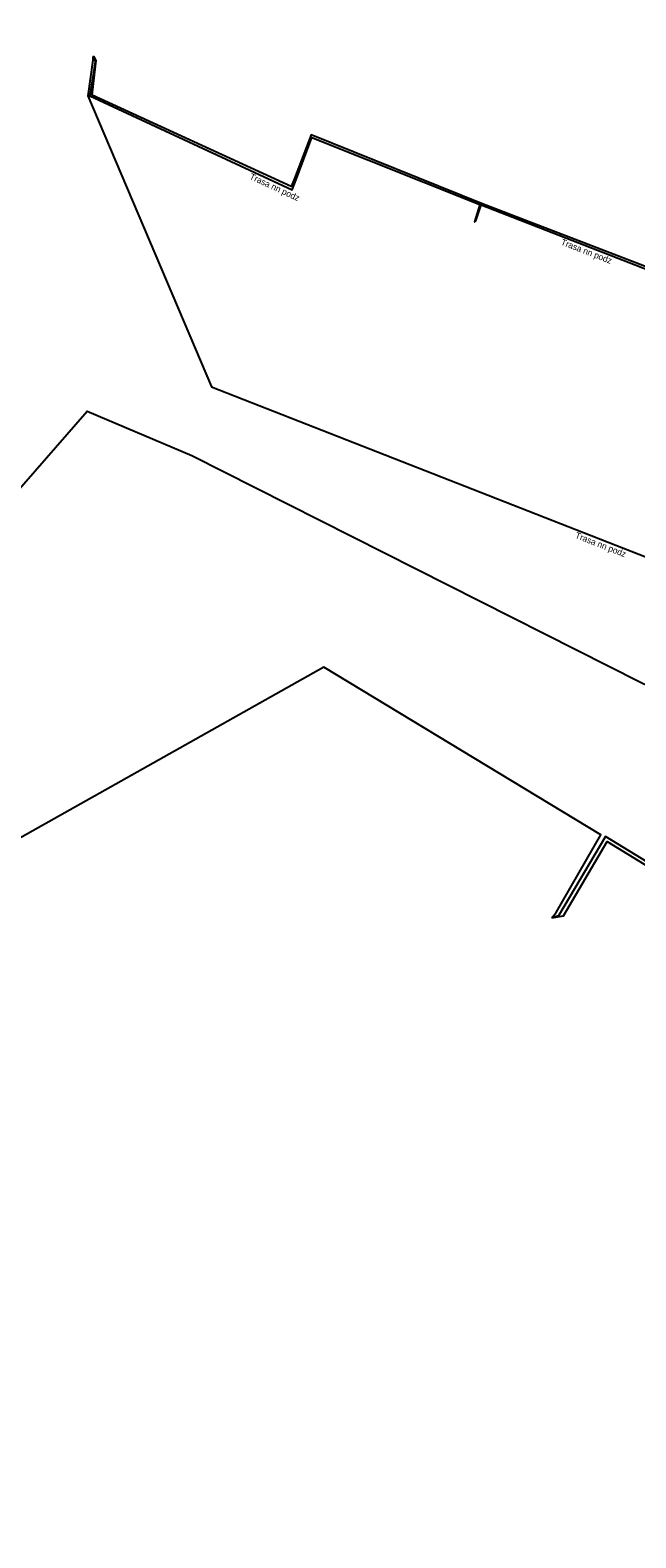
# Model space of a CAD drawing. Extents: x -875087 to -874407, y -1056142 to -1055396.
# Drawn here: x -874887.3 to -874839.3, y -1055781.1 to -1055661.4 of the extents above; entities that cross this region are included whole.
import ezdxf

# ---------------------------------------------------------------- set-up
doc = ezdxf.new("R2010")
doc.units = 0
for name, color, linetype in [('Popiskový text - Ostatní atributy Trasy', 7, 'Continuous'), ('Spojnice NN', 7, 'Continuous'), ('Spojnice VN', 7, 'Continuous')]:
    doc.layers.add(name, color=color, linetype=linetype)

msp = doc.modelspace()

# ---------------------------------------------------------------- linework, layer by layer
at = {"layer": 'Spojnice NN'}
for points in [[(-874845.94, -1055731.88), (-874845.61, -1055731.46), (-874842.04, -1055725.31), (-874864.03, -1055712), (-874900.7, -1055732.61), (-874967.78, -1055686.93), (-874987.15, -1055678.46), (-875041.7, -1055654.87), (-875087.2, -1055633.97), (-875087.28, -1055633.14), (-875080.46, -1055597.61), (-875077.09, -1055578.01), (-875076.82, -1055576.68), (-875075.98, -1055574.23)], [(-874882.28, -1055663.5), (-874882.36, -1055663.59), (-874882.36, -1055663.82), (-874882.76, -1055666.65), (-874872.96, -1055689.73), (-874796.22, -1055719.8), (-874798.83, -1055725.48), (-874799.67, -1055725.09), (-874804.68, -1055720.7), (-874805.36, -1055720.41)], [(-874882.28, -1055663.5), (-874882.18, -1055663.95), (-874882.6, -1055666.65), (-874866.55, -1055674.09), (-874866.23, -1055673.27), (-874864.99, -1055669.94), (-874851.66, -1055675.27), (-874852.09, -1055676.63), (-874852.1, -1055676.64)], [(-874805.36, -1055720.41), (-874804.9, -1055720.8), (-874799.91, -1055725.54), (-874798.64, -1055726.13), (-874789.31, -1055712.72), (-874783.85, -1055701.53), (-874805.68, -1055692.82), (-874813.18, -1055689.95), (-874832.53, -1055682.5), (-874851.52, -1055675.19), (-874865.05, -1055669.73), (-874866.37, -1055673.2), (-874866.62, -1055673.84), (-874882.43, -1055666.59), (-874882.1, -1055663.85), (-874882.28, -1055663.5)], [(-874852.1, -1055676.64), (-874852.08, -1055676.64), (-874851.97, -1055676.56), (-874851.55, -1055675.3), (-874832.62, -1055682.67), (-874833.06, -1055684.02), (-874833.07, -1055684.04)], [(-874805.36, -1055720.41), (-874805.14, -1055721.03), (-874800.48, -1055726.7), (-874798.71, -1055727.46), (-874800.13, -1055730), (-874809.2, -1055745.39), (-874829.16, -1055733.07), (-874841.67, -1055725.43), (-874845.42, -1055731.72), (-874845.94, -1055731.88)], [(-874845.94, -1055731.88), (-874845.02, -1055731.73), (-874841.56, -1055725.84), (-874809.29, -1055745.59), (-874821.17, -1055764.82), (-874859.09, -1055825.25), (-874862.21, -1055821.34), (-874862.58, -1055821)]]:
    msp.add_lwpolyline(points, dxfattribs=at)
at = {"layer": 'Spojnice VN'}
msp.add_lwpolyline([(-874889.46, -1055699.29), (-874882.83, -1055691.67), (-874874.5, -1055695.2), (-874838.9, -1055713.19), (-874822.22, -1055721.14), (-874812.85, -1055722.73), (-874801.88, -1055728.65), (-874799.88, -1055729.89), (-874798.06, -1055726.69), (-874800.02, -1055725.74), (-874805.04, -1055720.78), (-874805.36, -1055720.41)], dxfattribs=at)

# ---------------------------------------------------------------- texts
at = {"layer": 'Popiskový text - Ostatní atributy Trasy'}
for rotation, p in [(335.1414, (-874869.98, -1055673.22)), (338.7265, (-874845.27, -1055678.44)), (338.6, (-874844.14, -1055701.72))]:
    msp.add_text('Trasa nn podz', height=0.5, rotation=rotation, dxfattribs=at).set_placement(p)

doc.saveas('drawing.dxf')
